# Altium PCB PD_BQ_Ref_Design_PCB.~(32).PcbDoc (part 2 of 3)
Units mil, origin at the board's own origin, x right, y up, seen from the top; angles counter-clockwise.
Board outline 2000 x 3702.76 mil, 4 copper layers (Top Layer, Signal Layer 1, Signal Layer 2, Bottom Layer), stack 61.2 mil thick; 124 components, 53 nets, 359 pads, 494 vias.
Unrouted connection lines stored in the file: 227.
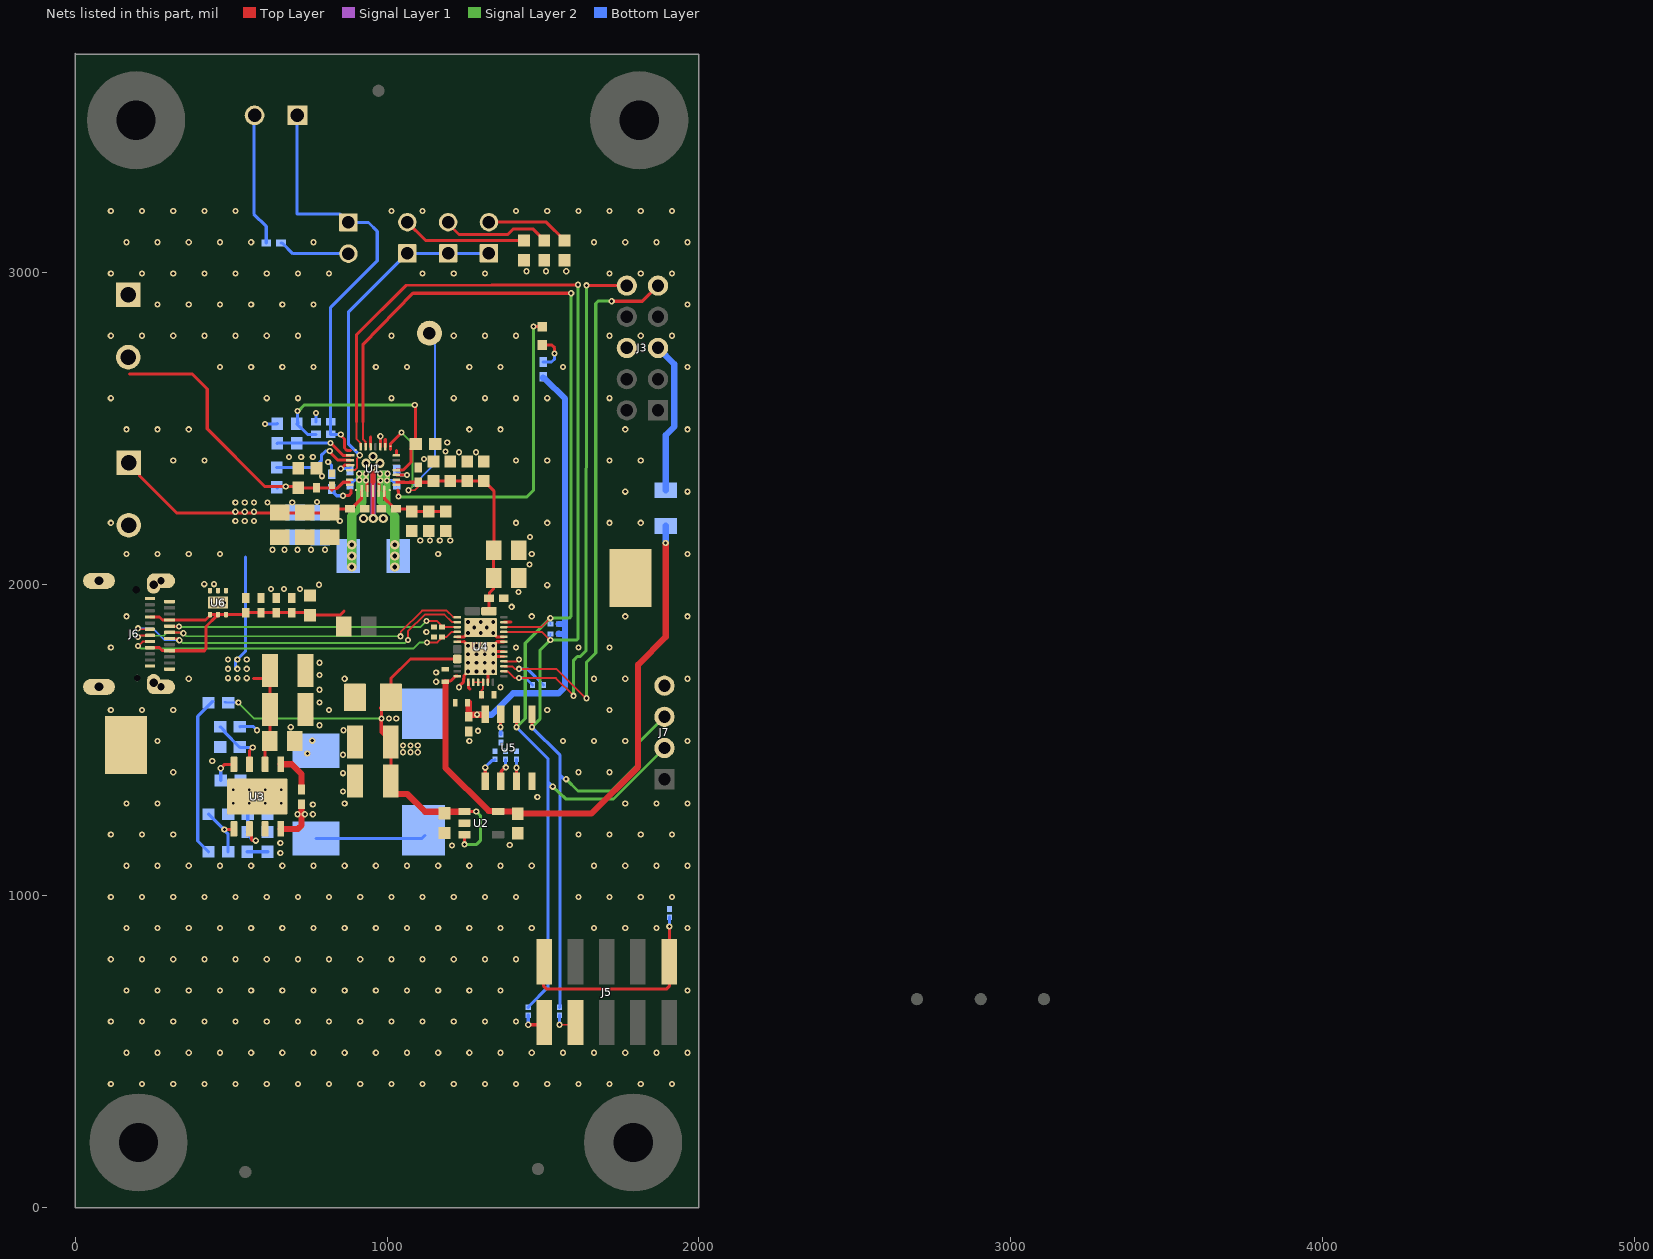
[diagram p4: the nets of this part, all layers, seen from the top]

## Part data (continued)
LOGO5: library part CMP-0074837-1, "IEC 61010-1 Hot Surface Warning"
NT1: library part CMP-0078142-3, "Single point connection between nets.", Manufacturer=N/A
R1: library part CMP-0022736-4, "RES, 100, 1%, 0.1 W, 0603", Manufacturer=Yageo, Power_W=100mW, Supplier Part Number 1=311-100HRCT-ND, TempCo="100 ppm/C", Tolerance_%=1%, Value2=0.1W, Value_Code=100R, ValueDisplayed=100
R2: library part CMP-0026232-2, "RES, 2.21 k, 1%, 0.063 W, AEC-Q200 Grade 0, 0402", Manufacturer=Vishay-Dale, Power_W=63mW, Supplier Part Number 1=541-2.21KLCT-ND, TempCo="100 ppm/C", Tolerance_%=1%, Value2=0.063W, Value_Code=2k21, ValueDisplayed=2.21k
R3: library part CMP-0026464-2, "RES, 5.23 k, 1%, 0.063 W, AEC-Q200 Grade 0, 0402", Manufacturer=Vishay-Dale, PartNumber=CRCW04025K23FKED, Power_W=63mW, Supplier Part Number 1=541-5.23KLCT-ND, TempCo="100 ppm/C", Tolerance_%=1%, Value2=0.063W, Value_Code=5k23, ValueDisplayed=5.23k
R4: library part CMP-0022788-4, "RES, 137 k, 1%, 0.1 W, 0603", Manufacturer=Yageo, Power_W=100mW, Supplier Part Number 1=311-137KHRCT-ND, TempCo="100 ppm/C", Tolerance_%=1%, Value2=0.1W, Value_Code=137k
R5: library part CMP-0026284-2, "RES, 30.1 k, 1%, 0.063 W, AEC-Q200 Grade 0, 0402", Manufacturer=Vishay-Dale, PartNumber=CRCW040230K1FKED, Power_W=63mW, Supplier Part Number 1=541-30.1KLCT-ND, TempCo="100 ppm/C", Tolerance_%=1%, Value2=0.063W, Value_Code=30k1, ValueDisplayed=30.1k
R6: library part CMP-0022735-5, "RES, 100 k, 1%, 0.1 W, 0603", Manufacturer=Yageo, Power_W=100mW, Supplier Part Number 1=311-100KHRCT-ND, TempCo="100 ppm/C", Tolerance_%=1%, Value2=0.1W, Value_Code=100k
R7: library part CMP-0025958-3, "RES, 10.0 k, 1%, 0.063 W, AEC-Q200 Grade 0, 0402", Manufacturer=Vishay-Dale, PartNumber=CRCW040210K0FKED, Power_W=63mW, Supplier Part Number 1=541-10.0KLCT-ND, TempCo="100 ppm/C", Tolerance_%=1%, Value2=0.063W, Value_Code=10k0, ValueDisplayed=10.0k
R8: library part CMP-0023246-5, "RES, 6.04 k, 1%, 0.1 W, 0603", Manufacturer=Yageo, Power_W=100mW, Supplier Part Number 1=311-6.04KHRCT-ND, TempCo="100 ppm/C", Tolerance_%=1%, Value2=0.1W, Value_Code=6k04, ValueDisplayed=6.04k
R9: library part CMP-0022000-4, "RES, 10.5 k, 1%, 0.1 W, AEC-Q200 Grade 0, 0603", Manufacturer=Vishay-Dale, Power_W=100mW, Supplier Part Number 1=541-10.5KHCT-ND, TempCo="100 ppm/C", Tolerance_%=1%, Value2=0.1W, Value_Code=10k5, ValueDisplayed=10.5k
R10: library part CMP-0022089-4, "RES, 17.4 k, 1%, 0.1 W, AEC-Q200 Grade 0, 0603", Manufacturer=Vishay-Dale, Power_W=100mW, Supplier Part Number 1=541-17.4KHCT-ND, TempCo="100 ppm/C", Tolerance_%=1%, Value2=0.1W, Value_Code=17k4, ValueDisplayed=17.4k
R11: library part CMP-0017299-3, "RES, 10.0, 1%, 0.25 W, AEC-Q200 Grade 0, 1206", Manufacturer=Panasonic, Power_W=250mW, Supplier Part Number 1=P10.0FCT-ND, TempCo="100 ppm/C", Tolerance_%=1%, Value2=0.25W, Value_Code=10R0, ValueDisplayed=10.0
R12: library part CMP-0022483-4, "RES, 51.1, 1%, 0.1 W, AEC-Q200 Grade 0, 0603", Manufacturer=Vishay-Dale, Power_W=100mW, Supplier Part Number 1=541-51.1HCT-ND, TempCo="100 ppm/C", Tolerance_%=1%, Value2=0.1W, Value_Code=51R1, ValueDisplayed=51.1
R13: library part CMP-0022546-4, "RES, 665 k, 1%, 0.1 W, AEC-Q200 Grade 0, 0603", Manufacturer=Vishay-Dale, Power_W=100mW, Supplier Part Number 1=541-665KHCT-ND, TempCo="100 ppm/C", Tolerance_%=1%, Value2=0.1W, Value_Code=665k
R14: library part CMP-0021999-4, "RES, 10.2 k, 1%, 0.1 W, AEC-Q200 Grade 0, 0603", Manufacturer=Vishay-Dale, Power_W=100mW, Supplier Part Number 1=541-10.2KHCT-ND, TempCo="100 ppm/C", Tolerance_%=1%, Value2=0.1W, Value_Code=10k2, ValueDisplayed=10.2k
R15: library part CMP-0022036-4, "RES, 130 k, 1%, 0.1 W, AEC-Q200 Grade 0, 0603", Manufacturer=Vishay-Dale, Power_W=100mW, Supplier Part Number 1=541-130KHCT-ND, TempCo="100 ppm/C", Tolerance_%=1%, Value2=0.1W, Value_Code=130k
R16: library part CMP-0022137-4, "RES, 1.96 k, 1%, 0.1 W, AEC-Q200 Grade 0, 0603", Manufacturer=Vishay-Dale, Power_W=100mW, Supplier Part Number 1=541-1.96KHCT-ND, TempCo="100 ppm/C", Tolerance_%=1%, Value2=0.1W, Value_Code=1k96, ValueDisplayed=1.96k
R17: library part CMP-0022360-4, "RES, 37.4 k, 1%, 0.1 W, AEC-Q200 Grade 0, 0603", Manufacturer=Vishay-Dale, Power_W=100mW, Supplier Part Number 1=541-37.4KHCT-ND, TempCo="100 ppm/C", Tolerance_%=1%, Value2=0.1W, Value_Code=37k4, ValueDisplayed=37.4k
R21 R22 R24 R25: library part CMP-0027272-3, "RES, 2.20 k, 1%, 0.05 W, 0201", Manufacturer=Vishay-Dale, Power_W=50mW, Supplier Part Number 1=541-2.20KAABCT-ND, TempCo="100 ppm/C", Tolerance_%=1%, Value2=0.05W, Value_Code=2k20, ValueDisplayed=2.20k
R26 R27 R29: library part CMP-0027008-4, "RES, 0, 5%, 0.05 W, 0201", Manufacturer=Vishay-Dale, Power_W=50mW, Supplier Part Number 1=72M6743, TempCo=ppm/C, Tolerance_%=5%, Value2=0.05W, Value_Code=0000, ValueDisplayed=0
R28 R30 R31 R32: library part CMP-0027262-3, "RES, 10.0 k, 1%, 0.05 W, 0201", Manufacturer=Vishay-Dale, Power_W=50mW, Supplier Part Number 1=541-10.0KAABCT-ND, TempCo="100 ppm/C", Tolerance_%=1%, Value2=0.05W, Value_Code=10k0, ValueDisplayed=10.0k
SH-J1 SH-J2: library part CMP-0003623-1, "Shunt, 100mil, Gold plated, Black", Alternate Manufacturer=3M, Alternate PartNumber=969102-0000-DA, Manufacturer=Samtec, Supplier Part Number 1=SNT-100-BK-G-ND
TP1: library part CMP-0055137-1, "Test Point, Miniature, Red, TH", Color=Red, Manufacturer=Keystone, Supplier Part Number 1=36-5000-ND
TP2 TP3: library part CMP-0055153-1, "Test Point, Compact, SMT", Manufacturer=Keystone, Supplier Part Number 1=36-5016TR-ND
U1: library part CMP-0088656-1, "BQ2579x HotRod", Manufacturer="Texas Instruments", Operating Temperature Range=to
U2: library part CMP-0074640-3, "500-mA, Low IQ, Small Size, Low Dropout Regulator, DBV0005A (SOT-23-5)", Alternate Manufacturer="Texas Instruments"
U3: library part CMP-0067056-2, "3.5V to 28V Input, 5A, 570kHz Step-Down Converter with Eco-mode, DDA0008E (SOIC-8)", Alternate Manufacturer="Texas Instruments", Alternate PartNumber=TPS54531DDA
U4: library part CMP-0090338-5, "USB Type-C and USB PD Controller with Integrated Power Switches Optimized for Power Applications", Manufacturer="Texas Instruments", Max Supply Voltage=22V, Min Supply Voltage=3V, Operating Temperature Range="-40°C to +125°C"
U5: library part CMP-0005314-2, "256 kb I2C CMOS Serial EEPROM, SOIC-8", Manufacturer="ON Semiconductor", Supplier Part Number 1=CAT24C256WI-G-ND
U6: library part CMP-0077834-1, "22-V Precision Surge Protection Clamp, DRV0006A (WSON-6)", Alternate Manufacturer="Texas Instruments"
ZZ1: library part CMP-0003616-3

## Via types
v1: diameter 20, hole 10, Top Layer to Bottom Layer, tented both sides, 445 vias
v2: diameter 23.62, hole 11.81, Top Layer to Bottom Layer, 24 vias
v3: diameter 30, hole 15, Top Layer to Bottom Layer, tented both sides, 12 vias
v4: diameter 19.68, hole 7.87, Top Layer to Bottom Layer, tented both sides, 10 vias
v5: diameter 20, hole 10, Top Layer to Bottom Layer, 3 vias

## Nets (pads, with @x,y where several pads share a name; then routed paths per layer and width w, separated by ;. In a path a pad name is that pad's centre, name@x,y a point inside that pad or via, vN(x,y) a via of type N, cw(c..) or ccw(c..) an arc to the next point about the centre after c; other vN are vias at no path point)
AGND: C22.2 J3.6 J4.2 NT1.2 R5.1 R6.1 R7.1 R8.1 R9.1 R10.1 U1.10 U1.11 U1.13 | length 616.2
  Top Layer w10: 946.85,2472.44 946.97,2472.32 U1.13@946.97,2440.84 ; 978.35,2462.6 978.35,2440.96 U1.11@978.46,2440.84 ; 994.09,2464.57 994.21,2464.45 U1.10@994.21,2440.84
  Bottom Layer w10: J4.2@574.8,3503.94 572.83,3501.97 572.83,3187.01 612.2,3147.64 R7.1@612.2,3094.49 ; v1(608.27,2513.78) 646.84,2513.78 R6.1@647.82,2514.76 ; v1(771.65,2549.21) 771.65,2520.79 R5.1@771.77,2520.67 ; v1(811.02,2391.73) 821.97,2380.79 C22.2@821.97,2352.36
  other v1: 978.35,2474.41 1446.85,3003.94 1509.84,3003.94 1574.8,3003.94
BAT: C19.1 C20.1 C21.1 J2.2 R1.1 U1.22 U1.23 | length 977.6
  Top Layer w10: 173.23,2673.62 375.59,2673.62 423.23,2625.98 423.23,2498.03 608.27,2312.99 v1(674.83,2312.99) 710.75,2312.99 C21.1@714.68,2309.06 C20.1@773.74,2309.06 817.05,2309.06 822.95,2303.15 ; 822.95,2301.18 822.95,2303.15 ; 879.05,2326.77 859.37,2326.77 839.8,2307.2 827,2307.2 822.95,2303.15
  Bottom Layer w10: R1.1@645.67,2311.02 647.64,2309.06 651.57,2312.99 v1(674.83,2312.99)
C_CC1: C42.1 J6.A5 U4.28 | length 942.2
  Top Layer w6: J6.A5@302.17,1865.16 302.66,1864.67 332.19,1864.67 v1(332.68,1864.17) ; v1(1126.77,1881.89) 1159.35,1881.89 1176.38,1864.86 C42.1@1176.38,1862.2 1225.02,1862.2 U4.28@1225.2,1862.39
  Signal Layer 2 w6: v1(332.68,1864.17) 334.65,1862.2 1107.09,1862.2 v1(1126.77,1881.89)
C_CC2: C41.1 J6.B5 U4.29 | length 1095.8
  Top Layer w6: v1(200.79,1801.18) 215.55,1815.95 J6.B5@239.17,1815.95 ; v1(1127.95,1812.99) 1161.31,1812.99 1176.38,1828.06 C41.1@1176.38,1830.71 1190.94,1830.71 1206.87,1846.64 U4.29@1225.2,1846.64
  Signal Layer 2 w6: v1(200.79,1801.18) 203.43,1801.18 211.3,1793.31 1084.65,1793.31 1104.33,1812.99 v1(1127.95,1812.99)
C_USB_N: J6.A7 J6.B7 U4.27 | length 1182
  Top Layer w6: v1(200.79,1858.27) 203.74,1855.32 J6.B7@239.17,1855.32 ; J6.A7@302.17,1825.79 327.76,1825.79 v1(333.6,1819.94) ; v1(1066.93,1820.87) 1066.93,1848.43 1120.89,1902.39 1184.23,1902.39 1207.54,1879.07 1224.27,1879.07 U4.27@1225.2,1878.13
  Signal Layer 2 w6: v1(333.6,1819.94) 335.2,1819.94 344.12,1811.02 1056.41,1811.02 v1@1066.59,1821.2
  Bottom Layer w6: v1(200.79,1858.27) 248.03,1858.27 286.36,1819.94 v1(333.6,1819.94) ; v1@1066.26,1820.87 v1(1066.93,1820.87)
C_USB_P: J6.A6 J6.B6 U4.26 | length 1175.4
  Top Layer w6: v1(200.79,1830.27) 204.58,1830.27 209.94,1835.63 J6.B6@239.17,1835.63 ; J6.A6@302.17,1845.47 339.72,1845.47 342.67,1842.52 v1(346.46,1842.52) ; v1(1043.31,1832.68) 1043.85,1833.22 1043.85,1847 1112.2,1915.35 1190.95,1915.35 1211.48,1894.82 1224.27,1894.82 U4.26@1225.2,1893.88
  Signal Layer 2 w6: v1(200.79,1830.27) 204.58,1830.27 208.95,1834.65 283.46,1834.65 294.29,1845.47 335.94,1845.47 336.22,1845.2 343.78,1845.2 v1(346.46,1842.52) ; v1@344.98,1844 356.3,1832.68 v1(1043.31,1832.68)
GND: C2.1 C3.1 C4.1 C5.1 C6.2 C8.1 C9.1 C10.1 C11.2 C12.2 C13.2 C14.2 C15.2 C16.2 C17.2 C18.2 C19.2 C20.2 C21.2 C23.1 C24.1 C26.2 C27.2 C28.2 C29.2 C30.2 C31.2 C33.2 C34.2 C35.2 C36.2 C37.2 C38.2 C39.2 C40.2 C41.2 C42.2 C43.2 C44.2 C45.1 C46.1 C47.1 C48.1 D2.2 J1.2 J2.1 J6.A1 J6.A12 J6.B1 J6.B12 J6.S1 J6.S2 J6.S3 J6.S4 J7.4 NT1.1 R15.1 R16.1 R17.1 R28.1 R29.1 R30.1 R31.1 R32.1 TP2.1 TP3.1 U1.27 U2.2 U3.7 U3.9@583.66,1318.62 U4.5 U4.10 U4.11 U4.12 U4.14 U4.18 U4.31 U4.39 U5.4 U6.1 U6.2 U6.3 U6.7@457.68,1940.94 | length 894.8
  Top Layer w6: U4.10@1374.81,1752.15 1417.5,1752.15 v1(1423.23,1757.87)
  Top Layer w8: U4.31@1225.2,1815.14 1247.65,1815.14
  Top Layer w10: 954.84,2326.77 U1.27@954.84,2299.11 954.84,2210.63 v3(955.83,2210.63) ; v1(1230.31,1669.29) 1230.31,1672 1245.64,1687.32 1245.64,1696.6 1247.02,1697.98 1247.02,1707.03 1300.01,1760.02 U4.39@1300.01,1761.4 ; 1247.65,1815.14 U4.39@1300.01,1762.78 ; U4.39@1313.59,1747.82 U4.39@1300.01,1761.4 ; U4.39@1313.59,1774.98 U4.39@1300.01,1761.4 ; U4.39@1321.56,1784.33 1352.37,1815.14 U4.14@1374.81,1815.14 ; U4.39@1322.25,1783.65 U4.12@1374.81,1783.65 U4.39@1340.17,1783.65 ; U4.5@1323.63,1685.22 U4.39@1323.63,1737.78 ; U4.39@1340.17,1767.9 U4.11@1374.81,1767.9 ; U4.18@1374.81,1878.13 1397.82,1878.13
  Top Layer w15: 954.84,2326.77 v1@954.84,2372.23
  Signal Layer 1 w15: v1(954.84,2372.26) 954.96,2372.14 954.96,2211.49 v3(955.83,2210.63)
  other v1: 113.91,396.71 213.91,396.71 313.91,396.71 413.91,396.71 513.91,396.71 613.91,396.71 713.91,396.71 813.91,396.71 913.91,396.71 1013.91,396.71 1113.91,396.71 1213.91,396.71 1313.91,396.71 1413.91,396.71 1513.91,396.71 1613.91,396.71 1713.91,396.71 1813.91,396.71 1913.91,396.71 163.91,496.71 263.91,496.71 363.91,496.71 463.91,496.71 563.91,496.71 663.91,496.71 763.91,496.71 863.91,496.71 963.91,496.71 1063.91,496.71 1163.91,496.71 1263.91,496.71 1363.91,496.71 1463.91,496.71 1563.91,496.71 1663.91,496.71 1763.91,496.71 1863.91,496.71 1963.91,496.71 113.91,596.71 213.91,596.71 313.91,596.71 413.91,596.71 513.91,596.71 613.91,596.71 713.91,596.71 813.91,596.71 913.91,596.71 1013.91,596.71 1113.91,596.71 1213.91,596.71 1313.91,596.71 1413.91,596.71 163.91,696.71 263.91,696.71 363.91,696.71 463.91,696.71 563.91,696.71 663.91,696.71 763.91,696.71 863.91,696.71 963.91,696.71 1063.91,696.71 1163.91,696.71 1263.91,696.71 1363.91,696.71 1963.91,696.71 113.91,796.71 213.91,796.71 313.91,796.71 413.91,796.71 513.91,796.71 613.91,796.71 713.91,796.71 813.91,796.71 913.91,796.71 1013.91,796.71 1113.91,796.71 1213.91,796.71 1313.91,796.71 1413.91,796.71 163.91,896.71 263.91,896.71 363.91,896.71 463.91,896.71 563.91,896.71 663.91,896.71 763.91,896.71 863.91,896.71 963.91,896.71 1063.91,896.71 1163.91,896.71 1263.91,896.71 1363.91,896.71 1463.91,896.71 1663.91,896.71 1763.91,896.71 1863.91,896.71 1963.91,896.71 113.91,996.71 213.91,996.71 313.91,996.71 413.91,996.71 513.91,996.71 613.91,996.71 713.91,996.71 813.91,996.71 913.91,996.71 1013.91,996.71 1113.91,996.71 1213.91,996.71 1313.91,996.71 1413.91,996.71 1613.91,996.71 1713.91,996.71 1813.91,996.71 1913.91,996.71 163.91,1096.71 263.91,1096.71 363.91,1096.71 463.91,1096.71 563.91,1096.71 663.91,1096.71 763.91,1096.71 863.91,1096.71 963.91,1096.71 1063.91,1096.71 1163.91,1096.71 1263.91,1096.71 1363.91,1096.71 1463.91,1096.71 1663.91,1096.71 1763.91,1096.71 1863.91,1096.71 1963.91,1096.71 657.48,1137.8 1208.66,1161.42 1393.39,1163.39 657.48,1169.29 113.91,1196.71 213.91,1196.71 313.91,1196.71 1613.91,1196.71 1713.91,1196.71 1813.91,1196.71 1913.91,1196.71 163.91,1296.71 263.91,1296.71 863.91,1296.71 1763.91,1296.71 1863.91,1296.71 1963.91,1296.71 1481.97,1316.93 858.27,1334.65 858.27,1393.7 313.91,1396.71 1613.91,1396.71 1713.91,1396.71 438.98,1433.07 858.27,1452.76 744.09,1456.69 263.91,1496.71 1263.91,1496.71 1563.91,1496.71 1663.91,1496.71 1763.91,1496.71 1963.91,1496.71 759.84,1498.03 1291.34,1529.53 860.24,1531.5 690.94,1541.34 783.46,1547.24 113.91,1596.71 213.91,1596.71 313.91,1596.71 813.91,1596.71 1513.91,1596.71 1713.91,1596.71 783.46,1620.08 783.46,1661.42 1364.17,1669.29 1157.48,1687.01 363.91,1696.71 863.91,1696.71 1663.91,1696.71 1763.91,1696.71 1963.91,1696.71 783.46,1708.66 1157.48,1716.54 783.46,1748.03 113.91,1796.71 1413.91,1796.71 1613.91,1796.71 1713.91,1796.71 1125.98,1846.46 163.91,1896.71 1463.91,1896.71 1763.91,1896.71 1963.91,1896.71 1399.61,1927.17 1421.26,1974.41 627.95,1984.25 669.29,1984.25 720.47,1984.25 1513.91,1996.71 781.5,1998.03 413.39,2000 444.88,2000 1456.69,2062.99 163.91,2096.71 263.91,2096.71 363.91,2096.71 463.91,2096.71 1163.91,2096.71 1463.91,2096.71 1963.91,2096.71 632.17,2110.23 671.26,2110.24 712.6,2110.24 755.91,2110.24 801.18,2110.24 1106.3,2139.76 1137.8,2139.76 1169.29,2139.76 1202.76,2139.76 1458.66,2151.57 113.91,2196.71 1413.91,2196.71 1513.91,2196.71 1713.91,2196.71 1813.91,2196.71 1763.91,2296.71 1963.91,2296.71 791.34,2346.46 313.91,2396.71 413.91,2396.71 1413.91,2396.71 1513.91,2396.71 1713.91,2396.71 1813.91,2396.71 1118.11,2401.57 685.04,2407.48 724.41,2407.48 761.81,2407.48 1230.31,2423.23 1285.43,2423.23 1187.01,2425.2 1192.91,2454.72 163.91,2496.71 263.91,2496.71 363.91,2496.71 1263.91,2496.71 1363.91,2496.71 1763.91,2496.71 1963.91,2496.71 113.91,2596.71 613.91,2596.71 713.91,2596.71 1013.91,2596.71 1213.91,2596.71 1313.91,2596.71 1413.91,2596.71 1513.91,2596.71 1713.91,2596.71 463.91,2696.71 563.91,2696.71 663.91,2696.71 763.91,2696.71 963.91,2696.71 1063.91,2696.71 1263.91,2696.71 1363.91,2696.71 1563.91,2696.71 1963.91,2696.71 113.91,2796.71 213.91,2796.71 313.91,2796.71 413.91,2796.71 513.91,2796.71 613.91,2796.71 713.91,2796.71 1013.91,2796.71 1213.91,2796.71 1313.91,2796.71 1413.91,2796.71 1713.91,2796.71 1813.91,2796.71 1913.91,2796.71 263.91,2896.71 363.91,2896.71 463.91,2896.71 563.91,2896.71 663.91,2896.71 763.91,2896.71 1963.91,2896.71 113.91,2996.71 213.91,2996.71 313.91,2996.71 413.91,2996.71 513.91,2996.71 613.91,2996.71 713.91,2996.71 813.91,2996.71 1113.91,2996.71 1213.91,2996.71 1313.91,2996.71 1713.91,2996.71 1813.91,2996.71 1913.91,2996.71 163.91,3096.71 263.91,3096.71 363.91,3096.71 463.91,3096.71 563.91,3096.71 763.91,3096.71 1663.91,3096.71 1763.91,3096.71 1863.91,3096.71 1963.91,3096.71 113.91,3196.71 213.91,3196.71 313.91,3196.71 413.91,3196.71 513.91,3196.71 1013.91,3196.71 1113.91,3196.71 1413.91,3196.71 1513.91,3196.71 1613.91,3196.71 1713.91,3196.71 1813.91,3196.71 1913.91,3196.71
  other v2: 1259.85,1720.06 1286.62,1720.06 1313.39,1720.06 1340.17,1720.06 1259.85,1747.62 1286.62,1747.62 1313.39,1747.62 1340.17,1747.62 1259.85,1775.18 1286.62,1775.18 1313.39,1775.18 1340.17,1775.18 1259.85,1802.74 1286.62,1802.74 1313.39,1802.74 1340.17,1802.74
  other v3: 924.33,2210.63 987.32,2210.63 932.19,2387.78 977.48,2387.8 954.83,2409.65
  other v4: 506.89,1296.97 558.07,1296.97 609.25,1296.97 660.43,1296.97 506.89,1340.28 558.07,1340.28 609.25,1340.28 660.43,1340.28 436.02,1940.94 479.33,1940.94
I2C1_SCL: J3.9 R21.1 U4.9 | length 1911.4
  Top Layer w6: U4.9@1374.81,1736.4 1375.75,1735.46 1402.44,1735.46 1409.56,1728.35 v1(1423.23,1728.35) 1543.31,1728.35 1638.78,1632.87 v5@1639.76,1631.89
  Top Layer w10: v5(1720.47,2907.48) 1818.9,2907.48 J3.9@1869.09,2957.68
  Signal Layer 2 w10: v5(1639.76,1633.86) 1639.76,1749.59 1669.29,1779.12 1669.29,2900.35 1677.17,2908.23 1719.72,2908.23 v5(1720.47,2907.48)
  Bottom Layer w10: v1(1423.23,1728.35) 1450,1728.35 R21.1@1501.97,1676.38
I2C1_SDA: J3.10 R22.1 U4.8 | length 1783.2
  Top Layer w6: U4.8@1374.81,1720.65 1375.75,1719.72 1388.55,1719.72 1409.45,1698.82 v1(1423.23,1698.82) 1541.34,1698.82 v1(1598.43,1641.73) v1@1598.43,1639.76
  Top Layer w10: v5(1639.76,2958.66) J3.10@1769.09,2957.68
  Signal Layer 2 w10: v1(1598.43,1641.73) 1598.43,1755.91 1610.24,1767.72 1620.08,1767.72 1637.8,1785.43 1639.76,2960.63 v5(1639.76,2958.66)
  Bottom Layer w10: v1(1423.23,1698.82) 1444.09,1698.82 R22.1@1466.54,1676.38
I2C_SCL: J7.2 R24.2 R26.1 U1.14 U4.17 U5.6 | length 4218
  Top Layer w6: 923.23,2519.69 923.23,2464.57 930.28,2457.51 930.28,2441.78 U1.14@931.22,2440.84 ; U4.17@1374.81,1862.39 1495.03,1862.39 v1(1523.62,1890.98)
  Top Layer w10: 923.23,2519.69 923.23,2769.69 1082.68,2933.07 v1(1590.55,2933.07) ; v1(1415.35,1541.34) U5.6@1415.35,1582.21
  Signal Layer 2 w10: v1(1415.35,1541.34) 1443.23,1569.21 1443.23,1810.59 v1(1523.62,1890.98) 1583.89,1890.98 1590.55,1897.64 v1(1590.55,2933.07) ; v1(1531.5,1350.39) 1572.83,1311.02 1726.38,1311.02 J7.2@1889.76,1474.41
  Bottom Layer w6: v1(1523.62,1890.98) 1523.62,1872.83 R24.2@1524.41,1872.05
  Bottom Layer w10: v1(1415.35,1541.34) 1515.75,1440.94 1515.75,1364.17 ; R26.1@1452.76,642.91 1452.76,643.7 1456.02,646.97 1456.11,646.97 1515.75,706.61 1515.75,1364.17 ; v1(1531.5,1350.39) 1517.72,1364.17 1515.75,1364.17
I2C_SDA: J7.3 R25.2 R27.1 U1.15 U4.16 U5.5 | length 4321.3
  Top Layer w6: 901.57,2519.69 901.57,2466.54 914.54,2453.57 914.54,2441.78 U1.15@915.47,2440.84 ; U4.16@1374.81,1846.64 1495.88,1846.64 1521.65,1820.87 v1(1523.62,1820.87)
  Top Layer w10: 901.57,2519.69 901.57,2799.21 1061.02,2958.66 ; 1059.06,2958.66 v1@1610.24,2960.63 ; v1(1464.57,1541.34) U5.5@1464.57,1582.21
  Signal Layer 2 w10: v1(1464.57,1541.34) 1490.16,1566.93 1490.16,1787.4 v1(1523.62,1820.87) 1608.27,1820.87 1612.2,1824.8 v1(1612.2,2960.63) ; v1(1574.41,1374.41) 1612.2,1336.61 1718.5,1336.61 1803.15,1421.26 1803.15,1487.8 J7.3@1889.76,1574.41
  Bottom Layer w6: v1(1523.62,1820.87) 1523.62,1839.76 R25.2@1524.41,1840.55
  Bottom Layer w10: v1(1464.57,1541.34) 1555.12,1450.79 1555.12,1387.8 ; R27.1@1553.15,642.91 1555.12,644.88 1555.12,1387.8 ; v1(1574.41,1374.41) 1568.5,1374.41 1555.12,1387.8
ILIM_HIZ: R4.1 R6.2 U1.17 | length 250.9
  Top Layer w10: v1(818.9,2452.75) 858.36,2413.29 U1.17@882.01,2413.29
  Bottom Layer w10: R6.2@647.82,2451.77 648.81,2452.76 808.58,2452.76 v1(818.9,2452.75)
LDO_1V5: C37.1 U4.2 U4.3 U4.4 | length 83
  Top Layer w6: U4.2@1276.39,1685.22 U4.3@1292.13,1685.22 U4.4@1307.88,1685.22 1307.88,1664.18 1303.15,1659.45 1303.15,1636.14 C37.1@1302.83,1635.83
LDO_3V3: C36.1 C43.1 R2.2 R21.2 R22.2 R24.1 R25.1 U4.1 U5.8 | length 1507.2
  Top Layer w10: U4.1@1260.64,1685.22 1261.7,1684.16 1261.7,1667.43 1265.75,1663.39
  Top Layer w20: C43.1@1261.81,1574.8 1261.81,1578.74 C43.1@1263.62,1580.55 ; C36.1@1261.81,1620.91 1261.81,1580.55 C43.1@1263.62,1580.55 ; U5.8@1314.96,1582.6 1313.7,1581.34 v1(1288.67,1581.34) 1288.04,1580.71 1275.34,1580.71 1275.18,1580.55 C43.1@1263.62,1580.55
  Bottom Layer w20: v1@1289.37,1581.34 1335.28,1581.34 1404.33,1650.39 1474.41,1650.39 1503.94,1650.39 1533.46,1650.39 1550,1650.39 1570.87,1671.26 1570.87,1840.06 ; R2.2@1500,2662.4 1502.8,2659.61 1505.75,2659.61 1570.87,2594.49 1570.87,1872.62 ; R25.1@1550.39,1840.55 1550.89,1840.06 1570.87,1840.06 ; R24.1@1550.39,1872.05 1570.29,1872.05 1570.87,1872.62 ; 1570.87,1840.06 1570.87,1872.62
NetC1_1: C1.1 U1.4 | length 76.9
  Top Layer w10: U1.4@1029.65,2350.29 1063.99,2350.29 v1(1064.09,2350.39)
  Bottom Layer w10: C1.1@1030.63,2366.14 1030.63,2362.2 1042.54,2350.29 1063.99,2350.29 v1(1064.09,2350.39)
NetC1_2: C1.2 L1.1 U1.28 | length 640.5
  Top Layer w10: U1.28@972.56,2299.11 973.62,2300.18 973.62,2327.95 v1(978.35,2332.68)
  Signal Layer 2 w20: 1024.72,2216.54 1000.33,2240.93 ; v1(978.35,2332.68) 978.35,2353.46 v1(977.48,2354.33) v1(1001.1,2354.33) 1000,2353.23 v1(1000,2332.68) ; v1(978.35,2332.68) v1(1000,2332.68) ; v1(978.35,2332.68) 978.35,2264.68 977.46,2263.8 1000.33,2240.93 ; v1(1000,2332.68) 1000.33,2332.35 1000.33,2240.93
  Signal Layer 2 w30: v3(1024.72,2055.12) 1024.72,2216.54
  Bottom Layer w10: v1(1000,2332.68) 1016.85,2332.68 C1.2@1030.63,2318.9
  Bottom Layer w20: v1@977.48,2334.44 978.35,2333.58 v1(978.35,2332.68) v1(1000,2332.68) 1000,2353.23 v1(1001.1,2354.33) v1(977.48,2354.33) v1@977.48,2334.44
  other v3: 1024.72,2090.55 1024.72,2126.15
NetC7_1: C7.1 U1.19 | length 77
  Top Layer w10: v1(851.5,2370.08) 863.21,2381.79 U1.19@881.61,2381.79
  Bottom Layer w10: v1(851.5,2370.08) 853,2371.58 875.58,2371.58 C7.1@881.02,2366.14 ; C7.1@876.26,2370.08 C7.1@883.07,2376.89
NetC7_2: C7.2 L1.2 U1.26 | length 624.4
  Top Layer w10: v1(932.2,2333.25) 932.2,2331.94 936.06,2328.08 936.06,2300.18 U1.26@937.13,2299.11
  Signal Layer 2 w20: 886.93,2217.75 910.55,2241.37 v1(910.55,2334.07) 931.38,2334.07 v1(932.2,2333.25) ; 910.55,2248.03 924.33,2261.81 924.33,2325.37 v1(932.2,2333.25) ; v1@910.55,2335.05 v1(910.55,2354.33) v1(932.2,2354.33) v1(932.2,2333.25)
  Signal Layer 2 w30: v3(886.93,2055.12) v3(886.93,2090.55) v3(886.93,2126.01) 886.93,2217.75
  Bottom Layer w10: C7.2@881.02,2318.9 896.77,2334.65 897.35,2334.07 v1(910.55,2334.07)
  Bottom Layer w20: v1(910.55,2334.07) 931.38,2334.07 v1(932.2,2333.25) v1(932.2,2354.33) v1(910.55,2354.33) v1(910.55,2334.07)
NetC22_1: C22.1 U1.24 | length 87.7
  Top Layer w10: v1(858.27,2283.46) 858.92,2284.11 876.63,2284.11 884.81,2292.29 884.81,2300.23 883.86,2301.18
  Bottom Layer w10: C22.1@821.97,2305.12 828.78,2298.31 828.78,2293.26 838.57,2283.46 v1(858.27,2283.46)
NetC25_1: C25.1 U3.1 | length 129.4
  Top Layer w20: U3.1@658.66,1421.97 694.17,1421.97 725.65,1390.49 C25.1@725.65,1341.09
NetC25_2: C25.2 D2.1 L2.1 U3.8 | length 493.1
  Top Layer w20: U3.8@658.66,1215.28 658.78,1215.28 659.49,1214.57 713.93,1214.57 725.65,1226.28 C25.2@725.65,1293.85
  Bottom Layer w10: D2.1@771.65,1184.31 1111.48,1184.31 L2.1@1121.06,1193.9
  other v1: 712.6,1261.81 736.22,1261.81 761.81,1261.81 761.81,1293.31
NetC32_1: C32.1 C34.1 U3.6 | length 164.6
  Top Layer w10: U3.6@558.66,1215.28 564.49,1209.45 564.49,1181.57 568.9,1177.17 v1(578.74,1177.17)
  Bottom Layer w10: C32.1@552.69,1204.72 C32.1@552.69,1203.26 ; C34.1@553.15,1261.81 553.15,1206.69 C32.1@551.18,1204.72 C32.1@552.69,1203.26 ; C32.1@553.89,1195.11 555.41,1200.63 C32.1@552.69,1203.26 ; v1(578.74,1177.17) 570.97,1177.17 552.69,1195.44 C32.1@552.69,1203.26
NetC32_2: C32.2 R17.2 | length 65.9
  Bottom Layer w10: C32.2@551.18,1141.73 R17.2@617.13,1141.73
NetC33_1: C33.1 U3.4 | length 86.7
  Top Layer w10: v1(466.54,1409.45) 479.05,1421.97 U3.4@508.66,1421.97
  Bottom Layer w10: C33.1@466.54,1370.08 v1(466.54,1409.45)
NetC44_1: C44.1 C45.2 C46.2 C47.2 C48.2 J6.A4 J6.A9 J6.B4 J6.B9 L3.1 U6.4 U6.5 U6.6 | length 961.1
  Top Layer w10: J6.B4@239.17,1796.26 269.92,1796.26 279.45,1786.73 301.85,1786.73 J6.A9@302.17,1786.42 317.29,1786.42 413.43,1786.42 419.29,1792.28 419.29,1864.17 453.82,1898.7 456.77,1898.7 457.68,1899.61 U6.5@457.68,1902.56 ; J6.B9@239.17,1894.69 269.92,1894.69 279.45,1885.16 301.85,1885.16 J6.A4@302.17,1884.84 417.32,1884.84 432.09,1899.61 U6.4@432.09,1902.56 453.82,1902.56 U6.5@457.68,1902.56 ; 861.57,1913.39 848.78,1900.59 C44.1@752.95,1900.59 745.08,1908.46 C48.2@693.9,1908.46 C47.2@644.68,1908.46 C46.2@595.47,1908.46 C45.2@546.26,1908.46 540.35,1902.56 U6.6@483.27,1902.56 U6.5@457.68,1902.56
NetD1_1: D1.1 R2.1 | length 119.8
  Top Layer w10: D1.1@1498.03,2766.73 1499.02,2767.72 1527.56,2767.72 1537.4,2757.87 v1(1537.4,2740.16)
  Bottom Layer w10: R2.1@1500.98,2712.6 1527.56,2712.6 1537.4,2722.44 v1(1537.4,2740.16)
NetJ3_5: J3.5 R11.1 | length 489.2
  Bottom Layer w20: J3.5@1869.09,2757.68 1920.91,2705.87 1920.91,2505.55 1893.7,2478.35 R11.1@1893.7,2301.18
NetJ5_1: J5.1 R26.2 | length 85
  Top Layer w10: v1(1452.76,586.61) 1497.58,586.61 J5.1@1504.54,593.58
  Bottom Layer w10: v1(1452.76,586.61) R26.2@1452.76,616.93
NetJ5_2: J5.2 J5.10 R29.2 | length 712.5
  Top Layer w10: J5.2@1504.54,788.46 1502.06,785.98 1502.06,710.53 1511.81,700.79 1895.67,700.79 1905.42,710.53 1905.42,787.59 J5.10@1904.54,788.46 1905.51,789.43 v1(1905.51,901.57)
  Bottom Layer w10: v1(1905.51,901.57) R29.2@1905.51,931.89
NetJ5_3: J5.3 R27.2 | length 84.6
  Top Layer w6: v1(1553.15,586.61) 1597.58,586.61 J5.3@1604.54,593.58
  Bottom Layer w10: v1(1553.15,586.61) R27.2@1553.15,616.93
NetJP1_2: JP1.2 R8.2 | length 398.4
  Top Layer w10: JP1.2@1064.96,3161.22 1123.82,3102.36 R8.2@1438.98,3102.36
NetJP2_2: JP2.2 R9.2 | length 350.8
  Top Layer w10: JP2.2@1195.87,3161.22 1195.87,3156.5 1230.67,3121.69 1387.64,3121.69 1405.71,3139.76 1467.52,3139.76 1503.94,3103.35 R9.2@1503.94,3102.36
NetJP3_2: JP3.2 R10.2 | length 267.1
  Top Layer w10: JP3.2@1326.77,3161.22 1511.02,3161.22 1568.9,3103.35 R10.2@1568.9,3102.36
NetJP4_2: JP4.2 R7.2 | length 230.7
  Bottom Layer w10: R7.2@659.45,3094.49 663.39,3094.49 697.64,3060.24 JP4.2@875.98,3060.24
NetR1_2: R1.2 U1.18 | length 281.9
  Top Layer w10: v1(816.06,2427.17) 816.06,2424.09 841.87,2398.29 880.28,2398.29 U1.18@881.02,2397.54
  Bottom Layer w10: R1.2@645.67,2374.02 767.72,2374.02 789.37,2395.67 789.37,2413.29 789.32,2413.34 803.15,2427.17 v1(816.06,2427.17)
NetR12_1: R12.1 R14.2 | length 516.5
  Bottom Layer w10: R14.2@427.17,1141.73 392.72,1176.18 392.72,1575.79 R12.1@440.94,1624.02
NetR13_1: R13.1 R15.2 U3.3 | length 192.6
  Top Layer w10: U3.3@558.66,1421.97 558.66,1466.14 v1(568.9,1476.38)
  Bottom Layer w10: R13.1@464.57,1542.32 465.55,1542.32 479.25,1528.62 479.25,1524.68 526.57,1477.36 R15.2@527.56,1477.36 528.54,1476.38 v1(568.9,1476.38)
NetR14_1: R14.1 R16.2 U3.5 | length 179
  Top Layer w10: v1(477.85,1212.6) 478.73,1213.47 506.86,1213.47 U3.5@508.66,1215.28
  Bottom Layer w10: R16.2@427.17,1261.81 428.15,1261.81 477.36,1212.6 v1(477.85,1212.6) 477.85,1209.89 490.16,1197.59 R14.1@490.16,1141.73
NetR28_2: R28.2 U5.C | length 66
  Top Layer w10: v1@1364.57,1541.73 v1(1364.17,1541.34) 1364.17,1581.82 U5.C@1364.96,1582.6
  Bottom Layer w10: v1(1364.17,1541.34) 1364.67,1540.85 1364.67,1518.41 R28.2@1365.16,1517.91
NetR30_2: R30.2 U5.1 | length 87.4
  Top Layer w10: U5.1@1314.96,1368.04 v1(1314.96,1411.42)
  Bottom Layer w10: v1(1314.96,1411.42) 1314.96,1413.39 1335.31,1433.74 1343.19,1433.74 1346.46,1437.01 R30.2@1346.46,1437.8
NetR31_2: R31.2 U5.2 | length 76.5
  Top Layer w10: U5.2@1364.96,1368.04 1366.14,1369.22 1366.14,1399.61 1378.94,1412.4 v1(1380.91,1412.4)
  Bottom Layer w10: v1@1380.41,1412.89 R31.2@1380.41,1437.3
NetR32_2: R32.2 U5.3 | length 69.9
  Top Layer w10: U5.3@1414.96,1368.04 1415.05,1368.13 1415.05,1411.13 v1(1415.14,1411.22)
  Bottom Layer w10: v1(1415.14,1411.22) 1415.25,1411.33 1415.25,1437.69 R32.2@1415.35,1437.8
NetU4_15: U4.15 U4.30 U4.40 | length 233.7
  Top Layer w10: U4.30@1225.2,1830.89 1248.04,1830.89 U4.40@1277.96,1860.81 ; U4.40@1260.05,1842.9 U4.40@1277.96,1860.81 ; U4.15@1374.81,1830.89 1351.98,1830.89 ; U4.40@1277.96,1860.81 v2(1279.93,1860.81) U4.40@1300.01,1860.81 v2(1320.09,1860.81) 1322.06,1860.81 1351.98,1830.89 ; 1351.98,1830.89 1339.97,1842.9 1351.98,1830.89
  other v2: 1259.85,1843.09 1300.01,1843.09 1340.17,1843.09 1259.85,1878.53 1300.01,1878.53 1340.17,1878.53
P3V3: C24.2 C35.1 R11.2 U2.5 U4.38 | length 1869
  Top Layer w10: C35.1@1187.01,1686.69 1189.51,1689.19 1203.74,1689.19 1219.46,1704.91 U4.38@1225.2,1704.91
  Top Layer w20: C35.1@1187.01,1685.04 1187.01,1411.42 1325.85,1272.58 1354.49,1272.58 U2.5@1356.3,1270.76 ; U2.5@1358.11,1270.76 1412.57,1270.76 C24.2@1419.46,1263.87 1655.61,1263.87 1805.12,1413.39 1805.12,1742.13 1893.7,1830.71 v1(1893.7,2131.89)
  Bottom Layer w20: v1(1893.7,2131.89) R11.2@1893.7,2187.01
PMID: C8.2 C9.2 C10.2 C11.1 U1.29 | length 238.5
  Top Layer w10: U1.29@990.28,2298.13 991.18,2297.22 991.18,2275.67 1017.91,2248.94 1017.91,2246.97 1023.74,2241.14 1070.98,2241.14 C10.2@1078.86,2233.27 C9.2@1133.98,2233.27 C8.2@1188.11,2233.27
PP5V: C23.2 C26.1 C27.1 C28.1 L2.2 R12.2 U2.1 U2.3 U4.34 U4.35 U4.@1225.2,1760.02 | length 1669.2
  Top Layer w10: C28.1@1011.81,1369.09 1012.2,1369.49 1012.2,1494.09 981.22,1525.08 981.22,1567.83 v1(982.28,1568.9) 982.28,1599.02 978.35,1602.95 C26.1@1012.2,1636.81 ; C26.1@1028.94,1620.08 C26.1@1012.2,1636.81 ; U4.@1225.2,1760.02 1074.98,1760.02 1012.2,1697.24 C26.1@1012.2,1636.81 ; v1(1248.03,1165.35) U2.3@1248.03,1195.96 ; U2.1@1248.03,1270.76 1248.2,1270.93 1285.9,1270.93 v1(1286.06,1271.1)
  Top Layer w20: C28.1@1011.81,1369.09 1011.81,1342.36 1027.4,1326.77 1064.96,1326.77 1122.05,1269.69 1179.23,1269.69 C23.2@1184.05,1264.86 1188.88,1269.68 1246.95,1269.68 U2.1@1248.03,1270.76
  Signal Layer 2 w6: v1(522.86,1620.08) 574.04,1568.9 v1(982.28,1568.9)
  Signal Layer 2 w10: v1(1248.03,1165.35) 1287.4,1165.35 1299.21,1177.17 1299.21,1257.87 1286.06,1271.02 v1(1286.06,1271.1)
  Bottom Layer w6: R12.2@478.35,1622.05 480.31,1620.08 482.28,1622.05 484.25,1620.08 v1(522.86,1620.08)
  other v1: 1051.18,1460.63 1074.8,1460.63 1098.43,1460.63 1051.18,1482.28 1074.8,1482.28 1098.43,1482.28 1005.91,1568.9 1029.53,1568.9
PPHV: C2.2 C3.2 C4.2 C5.2 C6.1 C38.1 C39.1 C40.1 TP1.1 U1.2 U1.3 U1.8 U1.9 U4.20 U4.21 U4.22 U4.@1326.64,1913.57 | length 1633.6
  Top Layer w6: 1028.66,2429.13 1029.65,2428.15 ; U1.2@1029.65,2318.8 1029.65,2326.77 U1.3@1029.65,2334.55 ; v1(1068.9,2301.18) 1088.7,2301.18 1107.4,2319.88 C6.1@1100.51,2326.77
  Top Layer w10: 1010.94,2432.11 1010.94,2450.79 ; U1.9@1010.94,2442.32 1010.94,2450.79 ; U1.8@1029.65,2415.35 1029.65,2428.15 ; 1032.6,2326.77 1055.5,2326.77 1055.81,2326.46 1072.38,2326.46 1072.69,2326.77 C6.1@1100.51,2326.77 1144.8,2326.77 C5.2@1148.74,2330.71 C4.2@1202.87,2330.71 C3.2@1257.01,2330.71 1311.14,2330.71 1342.69,2299.16 1342.69,2129.85 1340.88,2128.04 1340.88,2043.07 1342.69,2041.26 1341.17,2039.75 1341.17,1984.87 1327.97,1971.67 1327.97,1952.04 1326.64,1950.71 U4.@1326.64,1913.57 ; v1(1046.38,2486.22) 1010.94,2450.79
  Signal Layer 2 w6: v1(1046.38,2486.22) 1082.09,2450.5 1082.09,2314.38 v1(1068.9,2301.18)
  Bottom Layer w6: v1(1068.9,2301.18) 1153.54,2385.83 1153.54,2767.38 1135.83,2785.09 TP1.1@1135.83,2805.12
PROG: JP1.1 JP2.1 JP3.1 U1.20 | length 1073.5
  Top Layer w6: U1.20@880.04,2366.04 896.81,2366.04 903.3,2372.53 903.3,2402.87 912.35,2411.92 v1(912.35,2413.56)
  Bottom Layer w10: v1(912.35,2413.56) 875.98,2449.92 875.98,2872.24 JP1.1@1064.96,3061.22 JP2.1@1195.87,3061.22 JP3.1@1326.77,3061.22
REGN: C18.1 R3.2 R4.2 U1.5 | length 752.8
  Top Layer w10: U1.5@1029.65,2366.04 1051.31,2366.04 1076.97,2391.7 1076.97,2436.1 1090.67,2449.8 C18.1@1091.65,2449.8 1091.65,2571.73 v1(1088.58,2574.8)
  Signal Layer 2 w10: v1(712.6,2555.12) 714.57,2555.12 734.25,2574.8 v1(1088.58,2574.8)
  Bottom Layer w10: R4.2@710.68,2514.76 R4.2@710.68,2513.78 ; v1(712.6,2555.12) 712.6,2519.63 714.57,2517.66 R4.2@710.68,2513.78 ; R3.2@771.77,2480.31 745.2,2480.31 725.43,2500.08 724.38,2500.08 R4.2@710.68,2513.78
STAT: D1.2 U1.1 | length 1022.6
  Top Layer w10: 1034.63,2301.12 1036.55,2299.2 v1(1036.55,2281.53) ; v1(1469.84,2826.13) 1494.73,2826.13 D1.2@1498.03,2822.83
  Signal Layer 2 w10: v1(1036.55,2281.53) 1038.46,2279.62 1045.53,2279.62 1045.63,2279.53 1448.23,2279.53 1469.84,2301.13 v1@1469.84,2830.71
SYS: C12.1 C13.1 C14.1 C15.1 C16.1 C17.1 C29.1 C30.1 C31.1 J1.1 R13.2 U1.25 U3.2 | length 1655.4
  Top Layer w10: J1.1@171.26,2389.37 205.63,2355 205.63,2347.52 324.8,2228.35 381.99,2228.35 382.34,2227.99 499.13,2227.99 513.31,2227.99 543.31,2227.99 v1@579.84,2227.99 ; 570.87,1696.85 C29.1@624.02,1696.85 ; v1@573.31,2227.99 v1@579.84,2227.99 ; U3.2@608.66,1421.97 608.66,1481.23 C31.1@624.19,1496.75 624.02,1496.92 C30.1@624.02,1598.43 ; C30.1@620.08,1602.36 C30.1@624.02,1598.43 ; C29.1@624.02,1722.44 C29.1@624.02,1696.85 ; U1.25@919.41,2299.11 918.5,2298.21 918.5,2275.67 894.72,2251.89 883.98,2241.14 833.15,2241.14 820,2227.99 739.29,2227.99 659.57,2227.99 v1@579.84,2227.99 ; C30.1@624.02,1598.43 C29.1@624.02,1696.85
  Bottom Layer w10: 513.91,1736.71 v1@513.91,1758.35 ; v1(519.69,1758.35) 545.28,1783.94 545.28,2086.79 ; R13.2@527.56,1542.32 528.54,1543.31 570.87,1543.31 v1(582.68,1531.5)
  other v1: 489.69,1698.35 519.69,1698.35 549.69,1698.35 489.69,1728.35 519.69,1728.35 549.69,1728.35 489.69,1758.35 549.69,1758.35 513.31,2202.28 543.31,2202.28 573.31,2202.28 848.43,2202.76 513.31,2232.28 543.31,2232.28 573.31,2232.28 616.14,2261.81 695.63,2261.9 513.31,2262.28 543.31,2262.28 573.31,2262.28 775.35,2263.17
TS: J4.1 JP4.1 R3.1 R5.2 U1.16 | length 1414.6
  Top Layer w10: v1(851.5,2480.32) 851.5,2477.61 863.31,2465.8 863.31,2436.83 871,2429.13 881.94,2429.13
  Bottom Layer w10: J4.1@712.6,3503.94 710.63,3501.97 710.63,3187.01 849.21,3187.01 JP4.1@875.98,3160.24 940.16,3160.24 968.5,3131.89 968.5,3037.4 819.02,2887.91 R5.2@819.02,2520.67 R3.1@819.02,2480.31 v1(851.5,2480.32)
